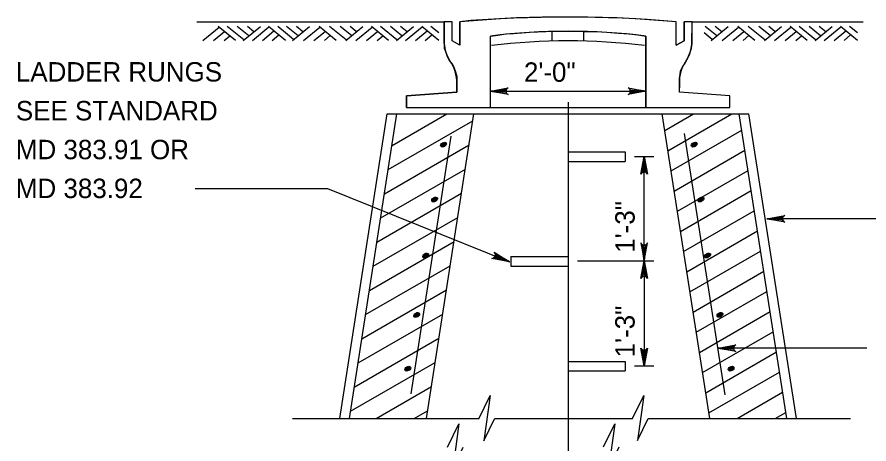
# Model space of a CAD drawing. Extents: x 0.9 to 8, y -0.9 to 9.3.
# Drawn here: x 0.93 to 3.564, y 3.449 to 4.768 of the extents above; entities that cross this region are included whole.
import ezdxf

# ---------------------------------------------------------------- set-up
doc = ezdxf.new("R2010")
doc.units = 0
for name, color, linetype in [('DETL-DIMS', 7, 'Continuous'), ('DETL-LINE', 7, 'Continuous'), ('DETL-NOTE', 7, 'Continuous'), ('DETL-PATT', 7, 'Continuous')]:
    doc.layers.add(name, color=color, linetype=linetype)

msp = doc.modelspace()

# ---------------------------------------------------------------- linework, layer by layer
at = {"layer": 'DETL-DIMS'}
for p, q in [((2.3935, 4.5387), (2.8739, 4.5387)), ((2.6337, 4.5047), (2.6337, 2.8837)), ((2.8396, 4.3373), (2.8984, 4.3373)), ((2.869, 4.0154), (2.869, 4.3373)), ((1.481, 4.2389), (1.8896, 4.2389)), ((1.8896, 4.2389), (2.4526, 4.0117)), ((3.7088, 4.145), (3.2487, 4.145)), ((2.6631, 4.0154), (2.8984, 4.0154)), ((2.869, 4.0154), (2.869, 3.6909)), ((3.5574, 3.7448), (3.0973, 3.7448)), ((2.8396, 3.6909), (2.8984, 3.6909))]:
    msp.add_line(p, q, dxfattribs=at)
for points in [[(2.3935, 4.5387), (2.4483, 4.549), (2.4441, 4.5461), (2.4419, 4.5424), (2.4413, 4.5387), (2.4419, 4.535), (2.4441, 4.5314), (2.4483, 4.5284), (2.3935, 4.5387), (2.4441, 4.5314), (2.4419, 4.535), (2.3935, 4.5387), (2.4413, 4.5387), (2.4419, 4.5424), (2.3935, 4.5387), (2.4441, 4.5461)], [(2.8739, 4.5387), (2.8191, 4.5284), (2.8233, 4.5314), (2.8255, 4.535), (2.8261, 4.5387), (2.8255, 4.5424), (2.8233, 4.5461), (2.8191, 4.549), (2.8739, 4.5387), (2.8233, 4.5461), (2.8255, 4.5424), (2.8739, 4.5387), (2.8261, 4.5387), (2.8255, 4.535), (2.8739, 4.5387), (2.8233, 4.5314)], [(2.869, 4.3373), (2.8793, 4.2825), (2.8764, 4.2867), (2.8727, 4.2889), (2.869, 4.2895), (2.8653, 4.2889), (2.8617, 4.2867), (2.8587, 4.2825), (2.869, 4.3373), (2.8617, 4.2867), (2.8653, 4.2889), (2.869, 4.3373), (2.869, 4.2895), (2.8727, 4.2889), (2.869, 4.3373), (2.8764, 4.2867)], [(3.2487, 4.145), (3.3035, 4.1553), (3.2993, 4.1523), (3.2971, 4.1487), (3.2965, 4.145), (3.2971, 4.1413), (3.2993, 4.1376), (3.3035, 4.1347), (3.2487, 4.145), (3.2993, 4.1376), (3.2971, 4.1413), (3.2487, 4.145), (3.2965, 4.145), (3.2971, 4.1487), (3.2487, 4.145), (3.2993, 4.1523)], [(2.869, 4.0154), (2.8793, 4.0702), (2.8764, 4.066), (2.8727, 4.0638), (2.869, 4.0632), (2.8653, 4.0638), (2.8617, 4.066), (2.8587, 4.0702), (2.869, 4.0154), (2.8617, 4.066), (2.8653, 4.0638), (2.869, 4.0154), (2.869, 4.0632), (2.8727, 4.0638), (2.869, 4.0154), (2.8764, 4.066)], [(2.4526, 4.0117), (2.398, 4.0227), (2.403, 4.0238), (2.4064, 4.0264), (2.4083, 4.0296), (2.4091, 4.0333), (2.4085, 4.0375), (2.4056, 4.0418), (2.4526, 4.0117), (2.4085, 4.0375), (2.4091, 4.0333), (2.4526, 4.0117), (2.4083, 4.0296), (2.4064, 4.0264), (2.4526, 4.0117), (2.403, 4.0238)], [(2.869, 4.0154), (2.8793, 3.9606), (2.8764, 3.9648), (2.8727, 3.967), (2.869, 3.9676), (2.8653, 3.967), (2.8617, 3.9648), (2.8587, 3.9606), (2.869, 4.0154), (2.8617, 3.9648), (2.8653, 3.967), (2.869, 4.0154), (2.869, 3.9676), (2.8727, 3.967), (2.869, 4.0154), (2.8764, 3.9648)], [(2.869, 3.6909), (2.8587, 3.7457), (2.8617, 3.7415), (2.8653, 3.7393), (2.869, 3.7387), (2.8727, 3.7393), (2.8764, 3.7415), (2.8793, 3.7457), (2.869, 3.6909), (2.8764, 3.7415), (2.8727, 3.7393), (2.869, 3.6909), (2.869, 3.7387), (2.8653, 3.7393), (2.869, 3.6909), (2.8617, 3.7415)], [(3.0973, 3.7448), (3.1522, 3.755), (3.1479, 3.7521), (3.1458, 3.7484), (3.1451, 3.7448), (3.1458, 3.7411), (3.1479, 3.7374), (3.1522, 3.7345), (3.0973, 3.7448), (3.1479, 3.7374), (3.1458, 3.7411), (3.0973, 3.7448), (3.1451, 3.7448), (3.1458, 3.7484), (3.0973, 3.7448), (3.1479, 3.7521)]]:
    msp.add_lwpolyline(points, dxfattribs=at)
at = {"layer": 'DETL-LINE'}
for p, q in [((1.4857, 4.7535), (2.2504, 4.7535)), ((2.2504, 4.6869), (2.2504, 4.7535)), ((2.2749, 4.6946), (2.2749, 4.7535)), ((2.2994, 4.6813), (2.2994, 4.7535)), ((2.968, 4.6813), (2.968, 4.7535)), ((2.9926, 4.6946), (2.9926, 4.7535)), ((3.0171, 4.6869), (3.0171, 4.7535)), ((3.0171, 4.7535), (3.5465, 4.7535)), ((2.5847, 4.6943), (2.5847, 4.7237)), ((2.6827, 4.6943), (2.6827, 4.7237)), ((2.2994, 4.6813), (2.2749, 4.6946)), ((2.3935, 4.4888), (2.3935, 4.7093)), ((2.8739, 4.4888), (2.8739, 4.7093)), ((2.968, 4.6813), (2.9926, 4.6946)), ((2.2896, 4.5363), (2.2896, 4.572)), ((2.9779, 4.5363), (2.9779, 4.572)), ((2.1337, 4.5252), (2.2896, 4.5363)), ((3.1337, 4.5252), (2.9779, 4.5363)), ((2.1337, 4.4888), (2.1337, 4.5252)), ((3.1337, 4.4888), (3.1337, 4.5252)), ((2.1337, 4.4888), (3.1337, 4.4888)), ((1.9278, 3.528), (2.0749, 4.4692)), ((1.9576, 3.528), (2.1047, 4.4692)), ((2.0749, 4.4692), (3.1925, 4.4692)), ((2.1958, 3.528), (2.3428, 4.4692)), ((3.0717, 3.528), (2.9246, 4.4692)), ((3.3098, 3.528), (3.1628, 4.4692)), ((3.3396, 3.528), (3.1925, 4.4692)), ((2.1482, 3.6046), (2.2725, 4.4002)), ((3.1197, 3.6015), (2.9937, 4.4083)), ((2.6337, 4.3515), (2.8102, 4.3515)), ((2.6337, 4.3515), (2.6337, 4.3221)), ((2.8102, 4.3515), (2.8102, 4.3221)), ((2.6337, 4.3221), (2.8102, 4.3221)), ((2.4572, 4.028), (2.6337, 4.028)), ((2.4572, 4.028), (2.4572, 3.9986)), ((2.6337, 4.028), (2.6337, 3.9986)), ((2.4572, 3.9986), (2.6337, 3.9986)), ((2.6337, 3.7044), (2.8102, 3.7044)), ((2.6337, 3.7044), (2.6337, 3.675)), ((2.8102, 3.7044), (2.8102, 3.675)), ((2.6337, 3.675), (2.8102, 3.675)), ((1.7817, 3.528), (2.3577, 3.528)), ((2.4062, 3.528), (2.8326, 3.528)), ((2.8811, 3.528), (3.5066, 3.528))]:
    msp.add_line(p, q, dxfattribs=at)
msp.add_lwpolyline([(2.2504, 4.7535), (2.2504, 4.6834), (2.2504, 4.6718), (2.2557, 4.6592), (2.2599, 4.6465), (2.2662, 4.6339), (2.2736, 4.6255), (2.2799, 4.6149), (2.2851, 4.6023), (2.2894, 4.5855), (2.2896, 4.5363), (2.1337, 4.5252), (2.1337, 4.4888), (2.3935, 4.4888), (2.3935, 4.7093), (2.4167, 4.7118), (2.4409, 4.716), (2.4651, 4.7171), (2.4903, 4.7192), (2.5156, 4.7213), (2.5398, 4.7223), (2.5651, 4.7234), (2.5872, 4.7244), (2.6827, 4.7234), (2.7208, 4.7234), (2.7534, 4.7213), (2.7892, 4.7181), (2.8218, 4.716), (2.8492, 4.7129), (2.8739, 4.7093), (2.8739, 4.4888), (3.1337, 4.4888), (3.1337, 4.5252), (2.9779, 4.5363), (2.9797, 4.5623), (2.9786, 4.5791), (2.9807, 4.5918), (2.9818, 4.6023), (2.9881, 4.6149), (2.9954, 4.6255), (2.9997, 4.6349), (3.006, 4.6476), (3.0112, 4.6592), (3.0144, 4.6718), (3.0165, 4.6844), (3.0171, 4.7535), (2.9926, 4.7535), (2.9926, 4.6946), (2.968, 4.6813), (2.968, 4.7535), (2.8786, 4.7602), (2.785, 4.7655), (2.6945, 4.7676), (2.5535, 4.7676), (2.4746, 4.7655), (2.4041, 4.7613), (2.3335, 4.7571), (2.2994, 4.7535), (2.2994, 4.6813), (2.2749, 4.6946), (2.2749, 4.7535)], close=True, dxfattribs=at)
for points in [[(2.3574, 3.5273), (2.3924, 3.5988), (2.3733, 3.4589), (2.4059, 3.5273)], [(2.8326, 3.528), (2.8676, 3.5994), (2.8485, 3.4595), (2.8811, 3.528)], [(2.2612, 3.4398), (2.2962, 3.5113), (2.2772, 3.3714), (2.3098, 3.4398)], [(2.743, 3.4404), (2.778, 3.5118), (2.759, 3.3719), (2.7915, 3.4404)]]:
    msp.add_lwpolyline(points, dxfattribs=at)
for centre, radius, start, end in [((2.6337, 0.9604), 3.8078, 84.9628, 95.0372), ((2.6337, 2.7551), 1.969, 82.9929, 97.0071), ((2.6337, 2.7551), 1.9395, 82.9929, 97.0071), ((2.3684, 4.6964), 0.1184, 184.6241, 212.5945), ((2.899, 4.6964), 0.1184, 327.4055, 355.3759)]:
    msp.add_arc(centre, radius, start, end, dxfattribs=at)
for centre, major_axis, start_param, end_param in [((2.2482, 4.5823), (0.014, -0.0676), 1.155753, 2.283479), ((3.0192, 4.5823), (-0.014, -0.0676), 3.999706, 5.127432)]:
    msp.add_ellipse(centre, major_axis=major_axis, ratio=0.578291, start_param=start_param, end_param=end_param, dxfattribs=at)
for centre, major_axis in [((2.2488, 4.374), (0.00849, 0.0049)), ((2.2488, 4.374), (0.00637, 0.00368)), ((2.2488, 4.374), (-0.00425, -0.00245)), ((2.2488, 4.374), (0.00212, 0.00123)), ((3.0237, 4.374), (0.00849, 0.0049)), ((3.0237, 4.374), (0.00637, 0.00368)), ((3.0237, 4.374), (-0.00425, -0.00245)), ((3.0237, 4.374), (0.00212, 0.00123)), ((2.2212, 4.2044), (0.00849, 0.0049)), ((2.2212, 4.2044), (0.00637, 0.00368)), ((2.2212, 4.2044), (-0.00425, -0.00245)), ((2.2212, 4.2044), (0.00212, 0.00123)), ((3.0445, 4.2044), (0.00849, 0.0049)), ((3.0445, 4.2044), (0.00637, 0.00368)), ((3.0445, 4.2044), (-0.00425, -0.00245)), ((3.0445, 4.2044), (0.00212, 0.00123)), ((2.1935, 4.0314), (0.00849, 0.0049)), ((2.1935, 4.0314), (0.00637, 0.00368)), ((2.1935, 4.0314), (-0.00425, -0.00245)), ((2.1935, 4.0314), (0.00212, 0.00123)), ((3.0652, 4.0314), (0.00849, 0.0049)), ((3.0652, 4.0314), (0.00637, 0.00368)), ((3.0652, 4.0314), (-0.00425, -0.00245)), ((3.0652, 4.0314), (0.00212, 0.00123)), ((2.1658, 3.8479), (0.00849, 0.0049)), ((2.1658, 3.8479), (0.00637, 0.00368)), ((2.1658, 3.8479), (-0.00425, -0.00245)), ((2.1658, 3.8479), (0.00212, 0.00123)), ((3.1033, 3.8479), (0.00849, 0.0049)), ((3.1033, 3.8479), (0.00637, 0.00368)), ((3.1033, 3.8479), (-0.00425, -0.00245)), ((3.1033, 3.8479), (0.00212, 0.00123)), ((2.1381, 3.6818), (0.00849, 0.0049)), ((2.1381, 3.6818), (0.00637, 0.00368)), ((3.1379, 3.6818), (0.00849, 0.0049)), ((3.1379, 3.6818), (0.00637, 0.00368)), ((2.1381, 3.6818), (-0.00425, -0.00245)), ((2.1381, 3.6818), (0.00212, 0.00123)), ((3.1379, 3.6818), (-0.00425, -0.00245)), ((3.1379, 3.6818), (0.00212, 0.00123))]:
    msp.add_ellipse(centre, major_axis=major_axis, ratio=0.65, dxfattribs=at)
at = {"layer": 'DETL-PATT'}
for p, q in [((1.5046, 4.6962), (1.5548, 4.7368)), ((1.5371, 4.6962), (1.571, 4.7239)), ((1.6057, 4.6962), (1.5523, 4.7389)), ((1.6315, 4.6975), (1.5802, 4.7389)), ((1.6467, 4.7099), (1.611, 4.7389)), ((1.6297, 4.6962), (1.6824, 4.739)), ((1.6626, 4.7227), (1.6428, 4.7389)), ((1.658, 4.6962), (1.7089, 4.7376)), ((1.6891, 4.6962), (1.7244, 4.7252)), ((1.7605, 4.6962), (1.7078, 4.7389)), ((1.7605, 4.719), (1.7361, 4.7389)), ((1.7849, 4.6989), (1.7598, 4.719)), ((1.799, 4.7103), (1.7633, 4.7389)), ((1.7817, 4.6962), (1.8344, 4.7389)), ((1.8142, 4.7226), (1.7944, 4.7389)), ((1.8156, 4.6962), (1.8662, 4.7369)), ((1.8482, 4.6962), (1.8824, 4.7239)), ((1.9167, 4.6962), (1.8637, 4.7389)), ((1.9478, 4.6974), (1.8966, 4.7389)), ((1.9641, 4.7107), (1.9295, 4.7389)), ((1.9464, 4.6962), (1.9991, 4.7389)), ((1.9789, 4.7231), (1.9598, 4.7389)), ((1.9779, 4.6962), (2.0281, 4.7368)), ((2.0104, 4.6962), (2.0443, 4.7239)), ((2.079, 4.6962), (2.0256, 4.7389)), ((2.1048, 4.6975), (2.0535, 4.7389)), ((2.12, 4.7099), (2.0843, 4.7389)), ((2.103, 4.6962), (2.1556, 4.739)), ((2.1359, 4.7227), (2.1161, 4.7389)), ((2.1313, 4.6962), (2.1822, 4.7376)), ((2.1624, 4.6962), (2.1977, 4.7252)), ((2.2338, 4.6962), (2.1811, 4.7389)), ((2.2338, 4.719), (2.2094, 4.7389)), ((3.0794, 4.6989), (3.0543, 4.719)), ((3.0935, 4.7103), (3.0578, 4.7389)), ((3.0762, 4.6962), (3.1288, 4.7389)), ((3.1087, 4.7226), (3.0889, 4.7389)), ((3.1101, 4.6962), (3.1606, 4.7369)), ((3.1426, 4.6962), (3.1769, 4.7239)), ((3.2112, 4.6962), (3.1582, 4.7389)), ((3.2423, 4.6974), (3.191, 4.7389)), ((3.2585, 4.7107), (3.2239, 4.7389)), ((3.2409, 4.6962), (3.2935, 4.7389)), ((3.2734, 4.7231), (3.2543, 4.7389)), ((3.2723, 4.6962), (3.3225, 4.7368)), ((3.3048, 4.6962), (3.3388, 4.7239)), ((3.3734, 4.6962), (3.32, 4.7389)), ((3.3992, 4.6975), (3.348, 4.7389)), ((3.4144, 4.7099), (3.3787, 4.7389)), ((3.3974, 4.6962), (3.4501, 4.739)), ((3.4303, 4.7227), (3.4105, 4.7389)), ((3.4257, 4.6962), (3.4766, 4.7376)), ((3.4568, 4.6962), (3.4922, 4.7252)), ((3.5282, 4.6962), (3.4755, 4.7389)), ((3.5282, 4.719), (3.5038, 4.7389)), ((1.5703, 4.6962), (1.5877, 4.7105)), ((1.7191, 4.6962), (1.7396, 4.713)), ((1.7632, 4.6962), (1.7632, 4.6962)), ((1.8803, 4.6962), (1.8984, 4.7109)), ((2.0436, 4.6962), (2.0609, 4.7105)), ((2.1924, 4.6962), (2.2129, 4.713)), ((3.0576, 4.6962), (3.0576, 4.6962)), ((3.1748, 4.6962), (3.1928, 4.7109)), ((3.3381, 4.6962), (3.3554, 4.7105)), ((3.4869, 4.6962), (3.5074, 4.713)), ((2.0894, 4.3714), (2.2586, 4.4692)), ((2.9327, 4.4176), (3.022, 4.4692)), ((2.9424, 4.3553), (3.1396, 4.4692)), ((2.0777, 4.2968), (2.3395, 4.4479)), ((2.9521, 4.293), (3.1706, 4.4191)), ((2.0661, 4.2221), (2.3278, 4.3732)), ((2.9619, 4.2307), (3.1803, 4.3568)), ((2.0544, 4.1475), (2.3162, 4.2986)), ((2.9716, 4.1684), (3.1901, 4.2945)), ((2.0427, 4.0728), (2.3045, 4.2239)), ((2.9814, 4.1061), (3.1998, 4.2322)), ((2.9911, 4.0438), (3.2095, 4.1699)), ((2.0311, 3.9981), (2.2928, 4.1493)), ((3.0008, 3.9815), (3.2193, 4.1076)), ((2.0194, 3.9235), (2.2812, 4.0746)), ((3.0106, 3.9192), (3.229, 4.0453)), ((2.0077, 3.8488), (2.2695, 4)), ((3.0203, 3.8569), (3.2387, 3.983)), ((1.9961, 3.7742), (2.2578, 3.9253)), ((3.03, 3.7946), (3.2485, 3.9207)), ((1.9844, 3.6995), (2.2462, 3.8506)), ((3.0398, 3.7323), (3.2582, 3.8584)), ((3.0495, 3.67), (3.2679, 3.7961)), ((1.9727, 3.6248), (2.2345, 3.776)), ((3.0592, 3.6077), (3.2777, 3.7338)), ((1.9611, 3.5502), (2.2228, 3.7013)), ((3.069, 3.5454), (3.2874, 3.6715)), ((2.0402, 3.528), (2.2112, 3.6267)), ((3.1565, 3.528), (3.2971, 3.6092)), ((2.1579, 3.528), (2.1995, 3.552)), ((3.2741, 3.528), (3.3069, 3.5469))]:
    msp.add_line(p, q, dxfattribs=at)

# ---------------------------------------------------------------- texts
at = {"layer": 'DETL-NOTE'}
for s, p in [('LADDER RUNGS', (0.9265, 4.5689)), ('2\'-0"', (2.4974, 4.5681)), ('SEE STANDARD', (0.9265, 4.4489)), ('MD 383.91 OR', (0.9265, 4.3289)), ('MD 383.92', (0.9265, 4.2089))]:
    msp.add_text(s, height=0.06, dxfattribs=at).set_placement(p)
for p in [(2.8396, 4.04), (2.8396, 3.7168)]:
    msp.add_text('1\'-3"', height=0.06, rotation=90, dxfattribs=at).set_placement(p)

doc.saveas('drawing.dxf')
